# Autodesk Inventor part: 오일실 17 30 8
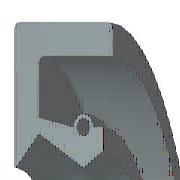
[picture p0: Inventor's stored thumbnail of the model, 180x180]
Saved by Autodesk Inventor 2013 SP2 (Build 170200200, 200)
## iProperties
Created: 2012-02
Part Number: 오일실 17 30 8
Material: 고무
Description: 오일-실
Document SubType Name: Modeling
Standard: KS B 2804
Designer: mduedu
Standards Organization: KS
Language: ko-KR
Size Designation: D - 17 30 8
Categories: <MemberInstance><Categories><Category DisplayName="샤프트 부품" InternalName="7f7aeb1f-a693-4053-b835-cee3144e0d98" Mnemonic="SHFT"><Category DisplayName="실링" Intern
Density: 0.93 g/cm^3
IsCustomPart: 1
Author: mduedu
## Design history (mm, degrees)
revolve "본체" stored, may be unused: angle "d17" = 90 deg
revolve "스프링1" stored, may be unused: angle "d18" = 90 deg
body "Solid1"
sketch "스케치1"
  geometry: L1 (0, 15)-(8, 15); L2 (8, 13.25)-(1.75, 13.25); L3 (1.75, 10.25)-(4.9, 8.5); L4 (4.9, 8.5)-(0, 8.5); L5 (0, 0)-(9.586, 0) reference; L6 (4.9, 8.5)-(6.3, 9.375); L7 (0, 18)-(0, -3) reference; L8 (-1.941, 0)-(11.507, 0) reference; L9 (4.2, 10.6)-(1.75, 11.21); L10 (1.75, 11.21)-(1.75, 13.25); L11 (0, 15)-(0, 8.588); L12 (4.9, 8.5)-(0, 8.5); L13 (1.75, 10.25)-(0.152, 8.528); L14 (8, 15)-(8, 13.25); L15 (5.6, 10.6)-(6.3, 10.6); L16 (6.3, 10.6)-(6.3, 9.375); C1 r 0.455 at (4.9, 10.6); A1 r 0.7 centre (4.9, 10.6) between (5.6, 10.6) and (4.2, 10.6); A2 r 0.088 centre (0.088, 8.588) between (0, 8.588) and (0.152, 8.528); 1 further point
  constraints: 28 end point, 5 horizontal alignment, 5 point on line, 4 point on circle, 4 vertical alignment, 3 centre point, 3 tangent, 2 collinear, 2 horizontal, 2 perpendicular, 1 coincident, 1 parallel
  dimensions: "d0" = 30 diameter of L1 L5 (= SD2); "d1" = 1.75 distance of L1.end L2.start (= SD); "d2" = 0.91 diameter of C1 (= SPDI); "d3" = 1.4 diameter of A1 (= SPDA); "d4" = 17 diameter of L3.end L5 (= NND); "d5" = 20.5 diameter of L3.start L5 (= TKDM); "d7" = 22.42 diameter of L9.end L5 (= TKDM + 0.24 x SWDT); "d8" = 1.75 distance between parallel lines of L11 L10 (= SD); "d9" = 4.9 distance from line of L11 C1.centre (= SPDST); "d10" = 21.2 diameter of C1.centre L5 (= HLDM); "d11" = 0.0875 radius of A2 (= 0.25 x LAB); "d12" = 6.3 distance between parallel lines of L11 L16 (= SDI); "d13" = 18.75 diameter of L6.end L5 (= ABDM); "d14" = 8 distance from line of L11 L1.end (= SWDT)
fillet "모깎기1" dims "d6" = 0.3 (= RR)
other parameters: "SD2" = 30 [user parameter; used in 1 equation term], "SWDT" = 8 [user parameter; used in 2 equation terms], "RR" = 0.3 [user parameter; used in 1 equation term], "SD" = 1.75 [user parameter; used in 2 equation terms], "NND" = 17 [user parameter; used in 1 equation term], "SPDA" = 1.4 [user parameter; used in 1 equation term], "SPDI" = 0.91 [user parameter; used in 1 equation term], "TKDM" = 20.5 [user parameter; used in 2 equation terms], "HLDM" = 21.2 [user parameter; used in 1 equation term], "ABDM" = 18.75 [user parameter; used in 1 equation term], "SDI" = 6.3 [user parameter; used in 1 equation term], "SPDST" = 4.9 [user parameter; used in 1 equation term], "LAB" = 0.35 [user parameter; used in 1 equation term], "d15" = 0, "d16" = 0, "d19" = 0
